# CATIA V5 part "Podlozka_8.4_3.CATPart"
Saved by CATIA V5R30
Part number: Podlozka_8.4_3
Definition: DIN 6340-8.4
Nomenclature: DIN 6340-8.4
Source: Unknown
Description: PART--DESC
Bounding box of the stored display mesh (mm): x 120.5 to 138.5, y 9.5 to 27.5, z 83.7 to 86.2
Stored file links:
  E:\Bakalarka\Model\Forma_v7\Podlozka_8.4_3.CATPart
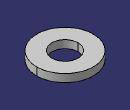
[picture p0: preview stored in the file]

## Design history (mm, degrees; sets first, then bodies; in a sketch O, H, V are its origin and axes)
Body1 "MANIFOLD_SOLID_BREP #3666" (main body)
  Solid1: solid without history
